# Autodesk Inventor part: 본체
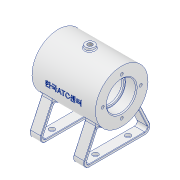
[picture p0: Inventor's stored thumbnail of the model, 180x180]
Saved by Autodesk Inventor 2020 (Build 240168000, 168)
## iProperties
Created: 2021-12
Part Number: 본체
Material: 알루미늄 6061
Document SubType Name: Modeling
Designer: MIRAE
Density: 2.7 g/cm^3
Appearance: 알루미늄 - 평지
Mass: 310.255 g
Surface Area: 355.122 cm^2
Volume: 114.909 cm^3
Author: MIRAE
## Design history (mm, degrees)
sketch "스케치1"
  geometry: L1 (-35, 0)-(35, 0); L2 (-35, 29)-(-35, 16); L3 (-35, 16)-(-23, 16); L4 (-23, 16)-(-23, 14); L5 (-23, 14)-(-21, 14); L6 (-21, 14)-(-21, 21); L7 (-21, 21)-(21, 21); L8 (21, 21)-(21, 14); L9 (21, 14)-(23, 14); L10 (23, 14)-(23, 16); L11 (23, 16)-(35, 16); L12 (35, 16)-(35, 29); L13 (35, 29)-(-35, 29); 1 further point
  constraints: 26 end point, 8 perpendicular, 5 point on line, 1 horizontal, 1 midpoint, 1 parallel, 1 vertical
  dimensions: "d0" = 70 distance of L1.start L1.end; "d1" = 35 distance of L1.start point (0, 0); "d2" = 70 distance of L12.end L2.start; "d3" = 58 diameter of L13 L1; "d4" = 32 diameter of L3 L1; "d5" = 28 diameter of L5 L1; "d7" = 42 distance between parallel lines of L8 L6; "d8" = 2 distance between parallel lines of L6 L4; "d9" = 2 distance between parallel lines of L10 L8; "d10" = 12 distance between parallel lines of L12 L10; "d11" = 42 diameter of L7 L1
revolve "회전1" sketch "스케치1" stored, may be unused: angle "d12" = 90 deg
sketch "스케치2"
  geometry: L1 (0, 0)-(-29, 0); L2 (0, 0)-(-30.07, -10.945); C1 r 14 at (0, 0) reference; C2 r 16 at (0, 0) reference; 2 further points
  constraints: 4 end point, 1 horizontal, 1 horizontal alignment, 1 other
  dimensions: "d15" = 32 distance of L1.start L2.end; "d16" = 20 deg angle of L1 L2
node "작업 평면1"
sketch "스케치3"
  geometry: C1 r 6 at (0, 0); 1 further point
  constraints: 1 centre point, 1 coincident
  dimensions: "d17" = 12 diameter of C1
extrude "돌출1" join sketch "스케치3" stored distance "d18" = 12; taper "d19" = 0 deg; dims "d45" = 4
node "작업 평면2"
sketch "스케치4"
  geometry: L1 (-17.993, 22.743)-(-55, 40); L2 (-55, 40)-(-55, -40); L3 (-55, -40)-(-17.993, -22.743); L4 (-29, 0)-(-55, 0); A1 r 29 centre (0, 0) between (-17.993, 22.743) and (-17.993, -22.743) reference; 1 further point
  constraints: 8 end point, 3 point on circle, 1 midpoint, 1 perpendicular, 1 point on line, 1 vertical
  dimensions: "d21" = 80 distance of L1.end L2.end; "d22" = 65 deg angle of L2 L1; "d23" = 65 deg angle of L2 L3; "d24" = 40 distance from line of L1.end L4; "d25" = 55 distance from line of point (0, 0) L2
extrude "돌출2" join sketch "스케치4" distance "d26" = 12; taper "d27" = 0 deg
sketch "스케치5"
  geometry: L1 (-20.574, -20.438)-(-35.291, -52); L2 (-35.291, -52)-(35.291, -52); L3 (35.291, -52)-(20.574, -20.438); L4 (-40, -55)-(40, -55) reference; L5 (-22.743, -17.993)-(-40, -55) reference; L6 (40, -55)-(22.743, -17.993) reference; A1 r 29 centre (0, 0) between (-22.743, -17.993) and (22.743, -17.993) reference; 1 further point
  constraints: 6 end point, 3 parallel, 2 point on circle
  dimensions: "d29" = 3 distance between parallel lines of L4 L2; "d30" = 3 distance between parallel lines of L5 L1; "d31" = 3 distance between parallel lines of L6 L3
extrude "돌출3" cut sketch "스케치5" stored distance "d32" = 0; taper "d33" = 0 deg
sketch "스케치6"
  geometry: L1 (0, -4.709)-(0, 75.291) reference; L2 (0, -4.709)-(-12, -4.709) reference; C1 r 3 at (-6, 17.291); C2 r 3 at (-6, 53.291); 1 further point
  constraints: 2 centre point
  dimensions: "d34" = 6 diameter of C1; "d35" = 6 diameter of C2; "d36" = 36 distance of C2.centre C1.centre; "d37" = 6 distance from line of L1 C1.centre; "d38" = 6 distance from line of L1 C2.centre; "d39" = 22 distance from line of L2 C1.centre
extrude "돌출4" cut sketch "스케치6" extent not by distance; stored distance "d40" = 74.738; taper "d41" = 0 deg
sketch "스케치7"
  geometry: C1 r 21 at (0, 0); 3 further points
  constraints: 1 centre point, 1 coincident, 1 vertical alignment, 1 other
  dimensions: "d42" = 42 diameter of C1
hole "구멍1" sketch "스케치7" at (0, 21) diameter "d43" = 3.242; stored, may be unused: countersink angle "d47" = 90 deg, drill point angle "d49" = 118 deg; dims "d44" = 8, "d45" = 4, "d46" = 2, "d48" = 10
fillet "모깎기1" dims "d53" = 6
fillet "모깎기2" dims "d54" = 3
fillet "모깎기3" dims "d55" = 0.5
fillet "모깎기4" dims "d56" = 3
node "작업 평면3"
sketch "스케치8"
  geometry: C1 r 5 at (0, 0); 1 further point
  constraints: 1 centre point, 1 coincident
  dimensions: "d58" = 10 diameter of C1
extrude "돌출5" join sketch "스케치8" stored distance "d59" = 12; taper "d60" = 0 deg; dims "d45" = 4
sketch "스케치9"
  geometry: C1 r 5 at (0, 0) reference; C2 r 1.5 at (0, 0); 3 further points
  constraints: 3 coincident, 1 centre point
  dimensions: "d78" = 3 diameter of C2
hole "구멍2" sketch "스케치9" at (0, 0) diameter "d61" = 5.1881; stored, may be unused: countersink angle "d65" = 90 deg, drill point angle "d67" = 118 deg; dims "d62" = 6, "d63" = 4, "d64" = 2, "d66" = 8
sketch "스케치11"
  geometry: L1 (0, 22.441)-(-2.594, 24) reference; L2 (0, 22.441)-(0, 21); L3 (21, 21)-(-21, 21) reference; L4 (-1.5, 23.343)-(-1.5, 21); 1 further point
  constraints: 4 end point, 2 point on line, 1 midpoint, 1 perpendicular, 1 vertical
  dimensions: "d79" = 3 diameter of L4 L2
revolve "회전2" sketch "스케치11" stored, may be unused: angle "d80" = 90 deg
fillet "모깎기5" dims "d81" = 0.3
fillet "모깎기6" dims "d82" = 3
chamfer "모따기2" distance "d83" = 1; stored, may be unused: second distance "d84" = 2, angle "d85" = 45 deg
sketch "스케치12"
  geometry: C1 r 6 at (0, 0) reference; 2 further points
  constraints: 1 coincident
hole "구멍4" sketch "스케치12" at (0, 0) diameter "d86" = 5.1881; stored, may be unused: countersink angle "d90" = 90 deg, drill point angle "d92" = 0 deg; dims "d87" = 6, "d88" = 6, "d89" = 2, "d91" = 20
fillet "모깎기7" dims "d93" = 1
node "작업 평면4"
sketch "스케치13"
  geometry: L1 (-35, -29)-(-35, 29) reference; L2 (-35, 29)-(35, 29) reference; 2 further points
  constraints: 1 other
  dimensions: "d94" = 35 distance from line of point (0, 0) L1; "d95" = 29 distance from line of L2 point (0, 0)
feature "엠보싱1" sketch "스케치13" dims "d0" = 70, "d1" = 35, "d2" = 70, "d3" = 58, "d4" = 32, "d5" = 28, "d7" = 42, "d8" = 2, "d9" = 2, "d10" = 12, "d11" = 42, "d96" = 0.5, "d97" = 0
node "솔리드1"
mirror "미러1"
pattern_circular "원형 패턴1" dims angle "d51" = 360 deg
mirror "미러2"
feature "A9D066F2-1C7D-4E18-AEED-F7BC21143FA4" dims "d61" = 5.1881, "d62" = 6, "d63" = 4, "d64" = 2, "d65" = 90 deg, "d66" = 8, "d67" = 118 deg
other parameters: "d57" = 32
